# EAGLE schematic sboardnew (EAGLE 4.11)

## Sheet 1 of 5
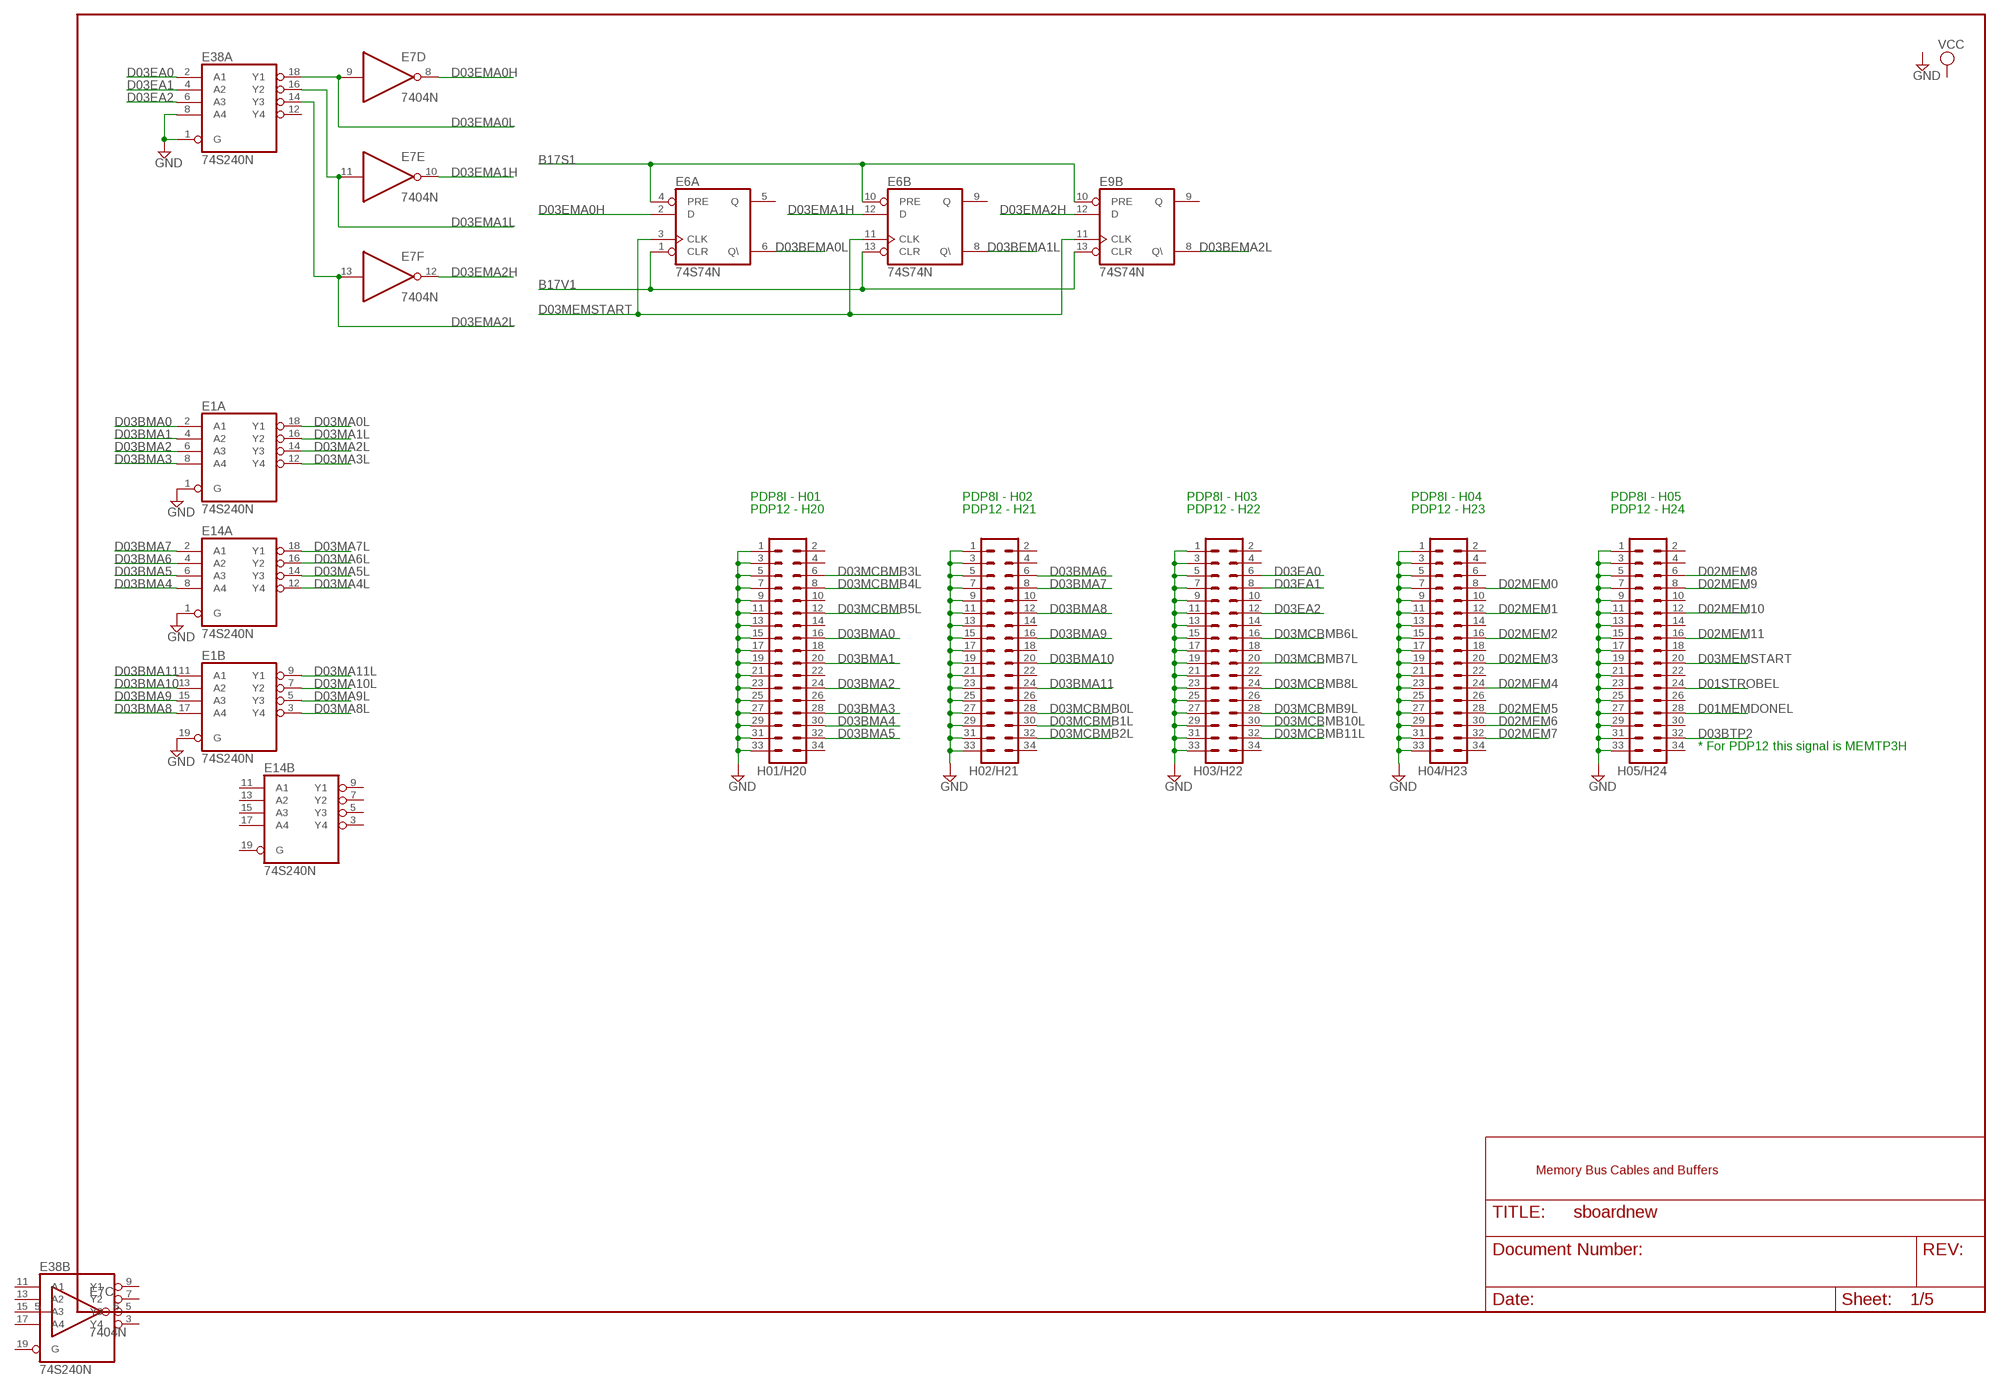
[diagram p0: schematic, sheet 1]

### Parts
E1  74S240N  [DIL20]
E6  74S74N  [DIL14]
E7  7404N  [DIL14]
E9  74S74N  [DIL14]
E14  74S240N  [DIL20]
E38  74S240N  [DIL20]
H01/H20  MA17-2  [MA17-2]
H02/H21  MA17-2  [MA17-2]
H03/H22  MA17-2  [MA17-2]
H04/H23  MA17-2  [MA17-2]
H05/H24  MA17-2  [MA17-2]

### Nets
B17S1: E6.4(A:PRE) E6.10(B:PRE) E9.10(B:PRE) ; also sheet 3,4
B17V1: E6.1(A:CLR) E6.13(B:CLR) E9.13(B:CLR) ; also sheet 3,4
D01MEMDONEL: H05/H24.28 ; also sheet 4
D01STROBEL: H05/H24.24 ; also sheet 4
D02MEM0: H04/H23.8 ; also sheet 3
D02MEM1: H04/H23.12 ; also sheet 3
D02MEM2: H04/H23.16 ; also sheet 3
D02MEM3: H04/H23.20 ; also sheet 3
D02MEM4: H04/H23.24 ; also sheet 3
D02MEM5: H04/H23.28 ; also sheet 3
D02MEM6: H04/H23.30 ; also sheet 3
D02MEM7: H04/H23.32 ; also sheet 3
D02MEM8: H05/H24.6 ; also sheet 3
D02MEM9: H05/H24.8 ; also sheet 3
D02MEM10: H05/H24.12 ; also sheet 3
D02MEM11: H05/H24.16 ; also sheet 3
D03BEMA0L: E6.6(A:Q\) ; also sheet 5
D03BEMA1L: E6.8(B:Q\) ; also sheet 5
D03BEMA2L: E9.8(B:Q\) ; also sheet 5
D03BMA0: E1.2(A:A1) H01/H20.16
D03BMA1: E1.4(A:A2) H01/H20.20
D03BMA2: E1.6(A:A3) H01/H20.24
D03BMA3: E1.8(A:A4) H01/H20.28
D03BMA4: E14.8(A:A4) H01/H20.30
D03BMA5: E14.6(A:A3) H01/H20.32
D03BMA6: E14.4(A:A2) H02/H21.6
D03BMA7: E14.2(A:A1) H02/H21.8
D03BMA8: E1.17(B:A4) H02/H21.12
D03BMA9: E1.15(B:A3) H02/H21.16
D03BMA10: E1.13(B:A2) H02/H21.20
D03BMA11: E1.11(B:A1) H02/H21.24
D03BTP2: H05/H24.32 ; also sheet 4
D03EA0: E38.2(A:A1) H03/H22.6
D03EA1: E38.4(A:A2) H03/H22.8
D03EA2: E38.6(A:A3) H03/H22.12
D03EMA0H: E6.2(A:D) E7.8(D:O) ; also sheet 4
D03EMA0L: E7.9(D:I) E38.18(A:Y1) ; also sheet 4
D03EMA1H: E6.12(B:D) E7.10(E:O) ; also sheet 4
D03EMA1L: E7.11(E:I) E38.16(A:Y2) ; also sheet 4
D03EMA2H: E7.12(F:O) E9.12(B:D) ; also sheet 4
D03EMA2L: E7.13(F:I) E38.14(A:Y3) ; also sheet 4
D03MA0L: E1.18(A:Y1) ; also sheet 5
D03MA1L: E1.16(A:Y2) ; also sheet 5
D03MA2L: E1.14(A:Y3) ; also sheet 5
D03MA3L: E1.12(A:Y4) ; also sheet 5
D03MA4L: E14.12(A:Y4) ; also sheet 5
D03MA5L: E14.14(A:Y3) ; also sheet 5
D03MA6L: E14.16(A:Y2) ; also sheet 5
D03MA7L: E14.18(A:Y1) ; also sheet 5
D03MA8L: E1.3(B:Y4) ; also sheet 5
D03MA9L: E1.5(B:Y3) ; also sheet 5
D03MA10L: E1.7(B:Y2) ; also sheet 5
D03MA11L: E1.9(B:Y1) ; also sheet 5
D03MCBMB0L: H02/H21.28 ; also sheet 2
D03MCBMB1L: H02/H21.30 ; also sheet 2
D03MCBMB2L: H02/H21.32 ; also sheet 2
D03MCBMB3L: H01/H20.6 ; also sheet 2
D03MCBMB4L: H01/H20.8 ; also sheet 2
D03MCBMB5L: H01/H20.12 ; also sheet 2
D03MCBMB6L: H03/H22.16 ; also sheet 2
D03MCBMB7L: H03/H22.20 ; also sheet 2
D03MCBMB8L: H03/H22.24 ; also sheet 2
D03MCBMB9L: H03/H22.28 ; also sheet 2
D03MCBMB10L: H03/H22.30 ; also sheet 2
D03MCBMB11L: H03/H22.32 ; also sheet 2
D03MEMSTART: E6.3(A:CLK) E6.11(B:CLK) E9.11(B:CLK) H05/H24.20 ; also sheet 4
GND [Power]: E1.1(A:G) E1.19(B:G) E14.1(A:G) E38.1(A:G) E38.8(A:A4) H01/H20.1 H01/H20.3 H01/H20.5 H01/H20.7 H01/H20.9 H01/H20.11 H01/H20.13 H01/H20.15 H01/H20.17 H01/H20.19 H01/H20.21 H01/H20.23 H01/H20.25 H01/H20.27 H01/H20.29 H01/H20.31 H01/H20.33 H02/H21.1 H02/H21.3 H02/H21.5 H02/H21.7 H02/H21.9 H02/H21.11 H02/H21.13 H02/H21.15 H02/H21.17 H02/H21.19 H02/H21.21 H02/H21.23 H02/H21.25 H02/H21.27 H02/H21.29 H02/H21.31 H02/H21.33 H03/H22.1 H03/H22.3 H03/H22.5 H03/H22.7 H03/H22.9 H03/H22.11 H03/H22.13 H03/H22.15 H03/H22.17 H03/H22.19 H03/H22.21 H03/H22.23 H03/H22.25 H03/H22.27 H03/H22.29 H03/H22.31 H03/H22.33 H04/H23.1 H04/H23.3 H04/H23.5 H04/H23.7 H04/H23.9 H04/H23.11 H04/H23.13 H04/H23.15 H04/H23.17 H04/H23.19 H04/H23.21 H04/H23.23 H04/H23.25 H04/H23.27 H04/H23.29 H04/H23.31 H04/H23.33 H05/H24.1 H05/H24.3 H05/H24.5 H05/H24.7 H05/H24.9 H05/H24.11 H05/H24.13 H05/H24.15 H05/H24.17 H05/H24.19 H05/H24.21 H05/H24.23 H05/H24.25 H05/H24.27 H05/H24.29 H05/H24.31 H05/H24.33 ; also sheet 3,4,5
Unconnected: E6.5(A:Q) E6.9(B:Q) H01/H20.2 H01/H20.4 H01/H20.10 H01/H20.14 H01/H20.18 H01/H20.22 H01/H20.26 H01/H20.34 H02/H21.2 H02/H21.4 H02/H21.10 H02/H21.14 H02/H21.18 H02/H21.22 H02/H21.26 H02/H21.34 H03/H22.2 H03/H22.4 H03/H22.10 H03/H22.14 H03/H22.18 H03/H22.22 H03/H22.26 H03/H22.34 H04/H23.2 H04/H23.4 H04/H23.6 H04/H23.10 H04/H23.14 H04/H23.18 H04/H23.22 H04/H23.26 H04/H23.34 H05/H24.2 H05/H24.4 H05/H24.10 H05/H24.14 H05/H24.18 H05/H24.22 H05/H24.26 H05/H24.30 H05/H24.34

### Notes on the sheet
- PDP8I - H01 | PDP8I - H02 | PDP8I - H03 | PDP8I - H04 | PDP8I - H05
- PDP12 - H20 | PDP12 - H21 | PDP12 - H22 | PDP12 - H23 | PDP12 - H24
- * For PDP12 this signal is MEMTP3H
- Memory Bus Cables and Buffers

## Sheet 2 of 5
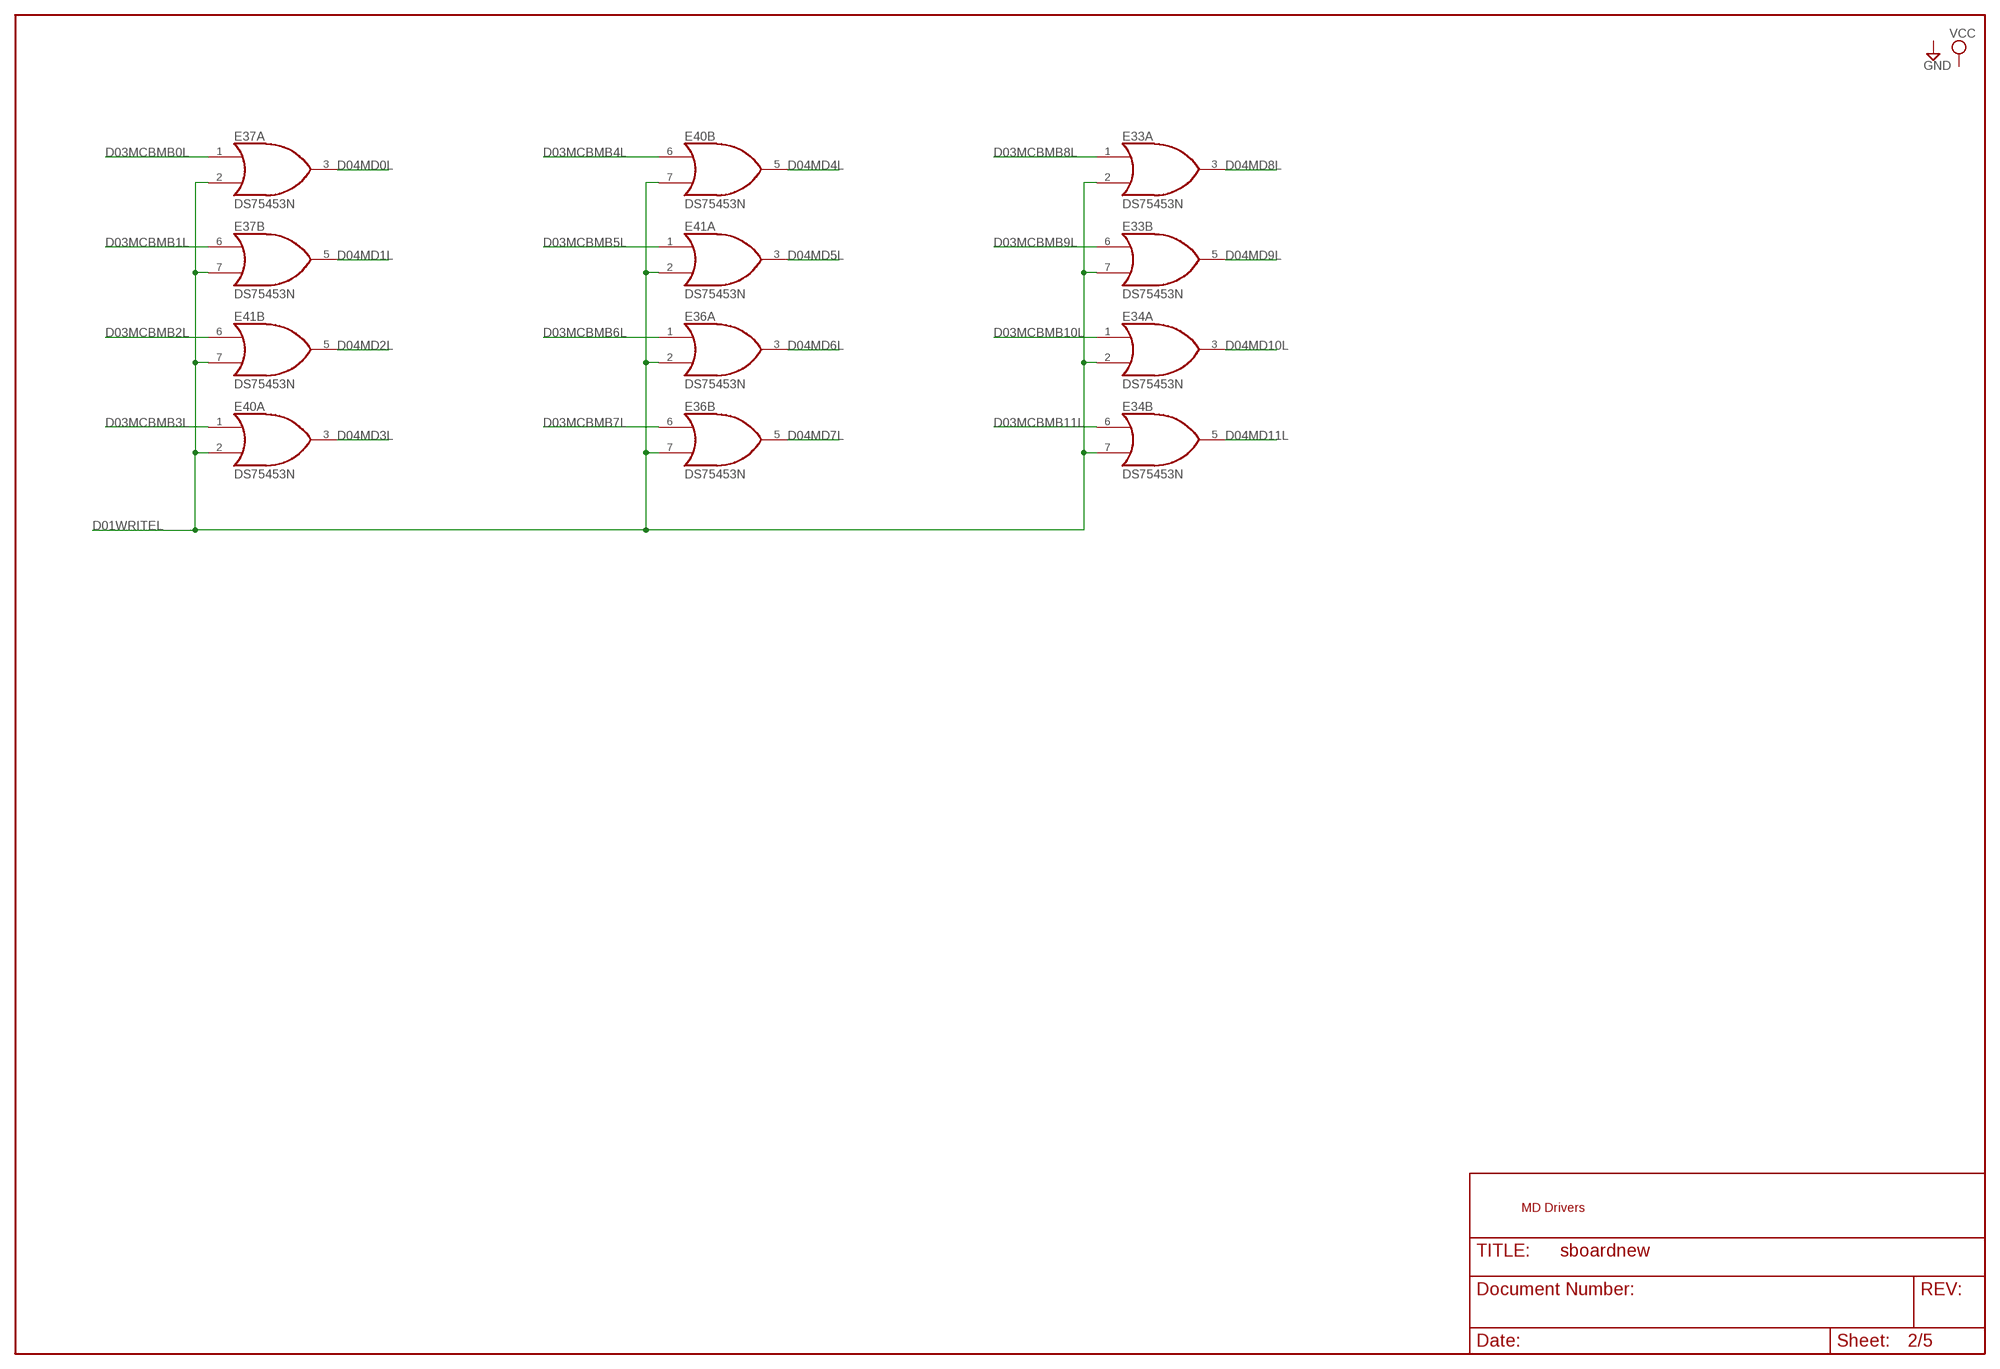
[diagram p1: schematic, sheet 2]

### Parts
E33  DS75453N  [DIL08]
E34  DS75453N  [DIL08]
E36  DS75453N  [DIL08]
E37  DS75453N  [DIL08]
E40  DS75453N  [DIL08]
E41  DS75453N  [DIL08]

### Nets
D01WRITEL: E33.2(A:I1) E33.7(B:I1) E34.2(A:I1) E34.7(B:I1) E36.2(A:I1) E36.7(B:I1) E37.2(A:I1) E37.7(B:I1) E40.2(A:I1) E40.7(B:I1) E41.2(A:I1) E41.7(B:I1) ; also sheet 3,5
D03MCBMB0L: E37.1(A:I0) ; also sheet 1
D03MCBMB1L: E37.6(B:I0) ; also sheet 1
D03MCBMB2L: E41.6(B:I0) ; also sheet 1
D03MCBMB3L: E40.1(A:I0) ; also sheet 1
D03MCBMB4L: E40.6(B:I0) ; also sheet 1
D03MCBMB5L: E41.1(A:I0) ; also sheet 1
D03MCBMB6L: E36.1(A:I0) ; also sheet 1
D03MCBMB7L: E36.6(B:I0) ; also sheet 1
D03MCBMB8L: E33.1(A:I0) ; also sheet 1
D03MCBMB9L: E33.6(B:I0) ; also sheet 1
D03MCBMB10L: E34.1(A:I0) ; also sheet 1
D03MCBMB11L: E34.6(B:I0) ; also sheet 1
D04MD0L: E37.3(A:O) ; also sheet 3,5
D04MD1L: E37.5(B:O) ; also sheet 3,5
D04MD2L: E41.5(B:O) ; also sheet 3,5
D04MD3L: E40.3(A:O) ; also sheet 3,5
D04MD4L: E40.5(B:O) ; also sheet 3,5
D04MD5L: E41.3(A:O) ; also sheet 3,5
D04MD6L: E36.3(A:O) ; also sheet 3,5
D04MD7L: E36.5(B:O) ; also sheet 3,5
D04MD8L: E33.3(A:O) ; also sheet 3,5
D04MD9L: E33.5(B:O) ; also sheet 3,5
D04MD10L: E34.3(A:O) ; also sheet 3,5
D04MD11L: E34.5(B:O) ; also sheet 3,5

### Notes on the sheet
- MD Drivers

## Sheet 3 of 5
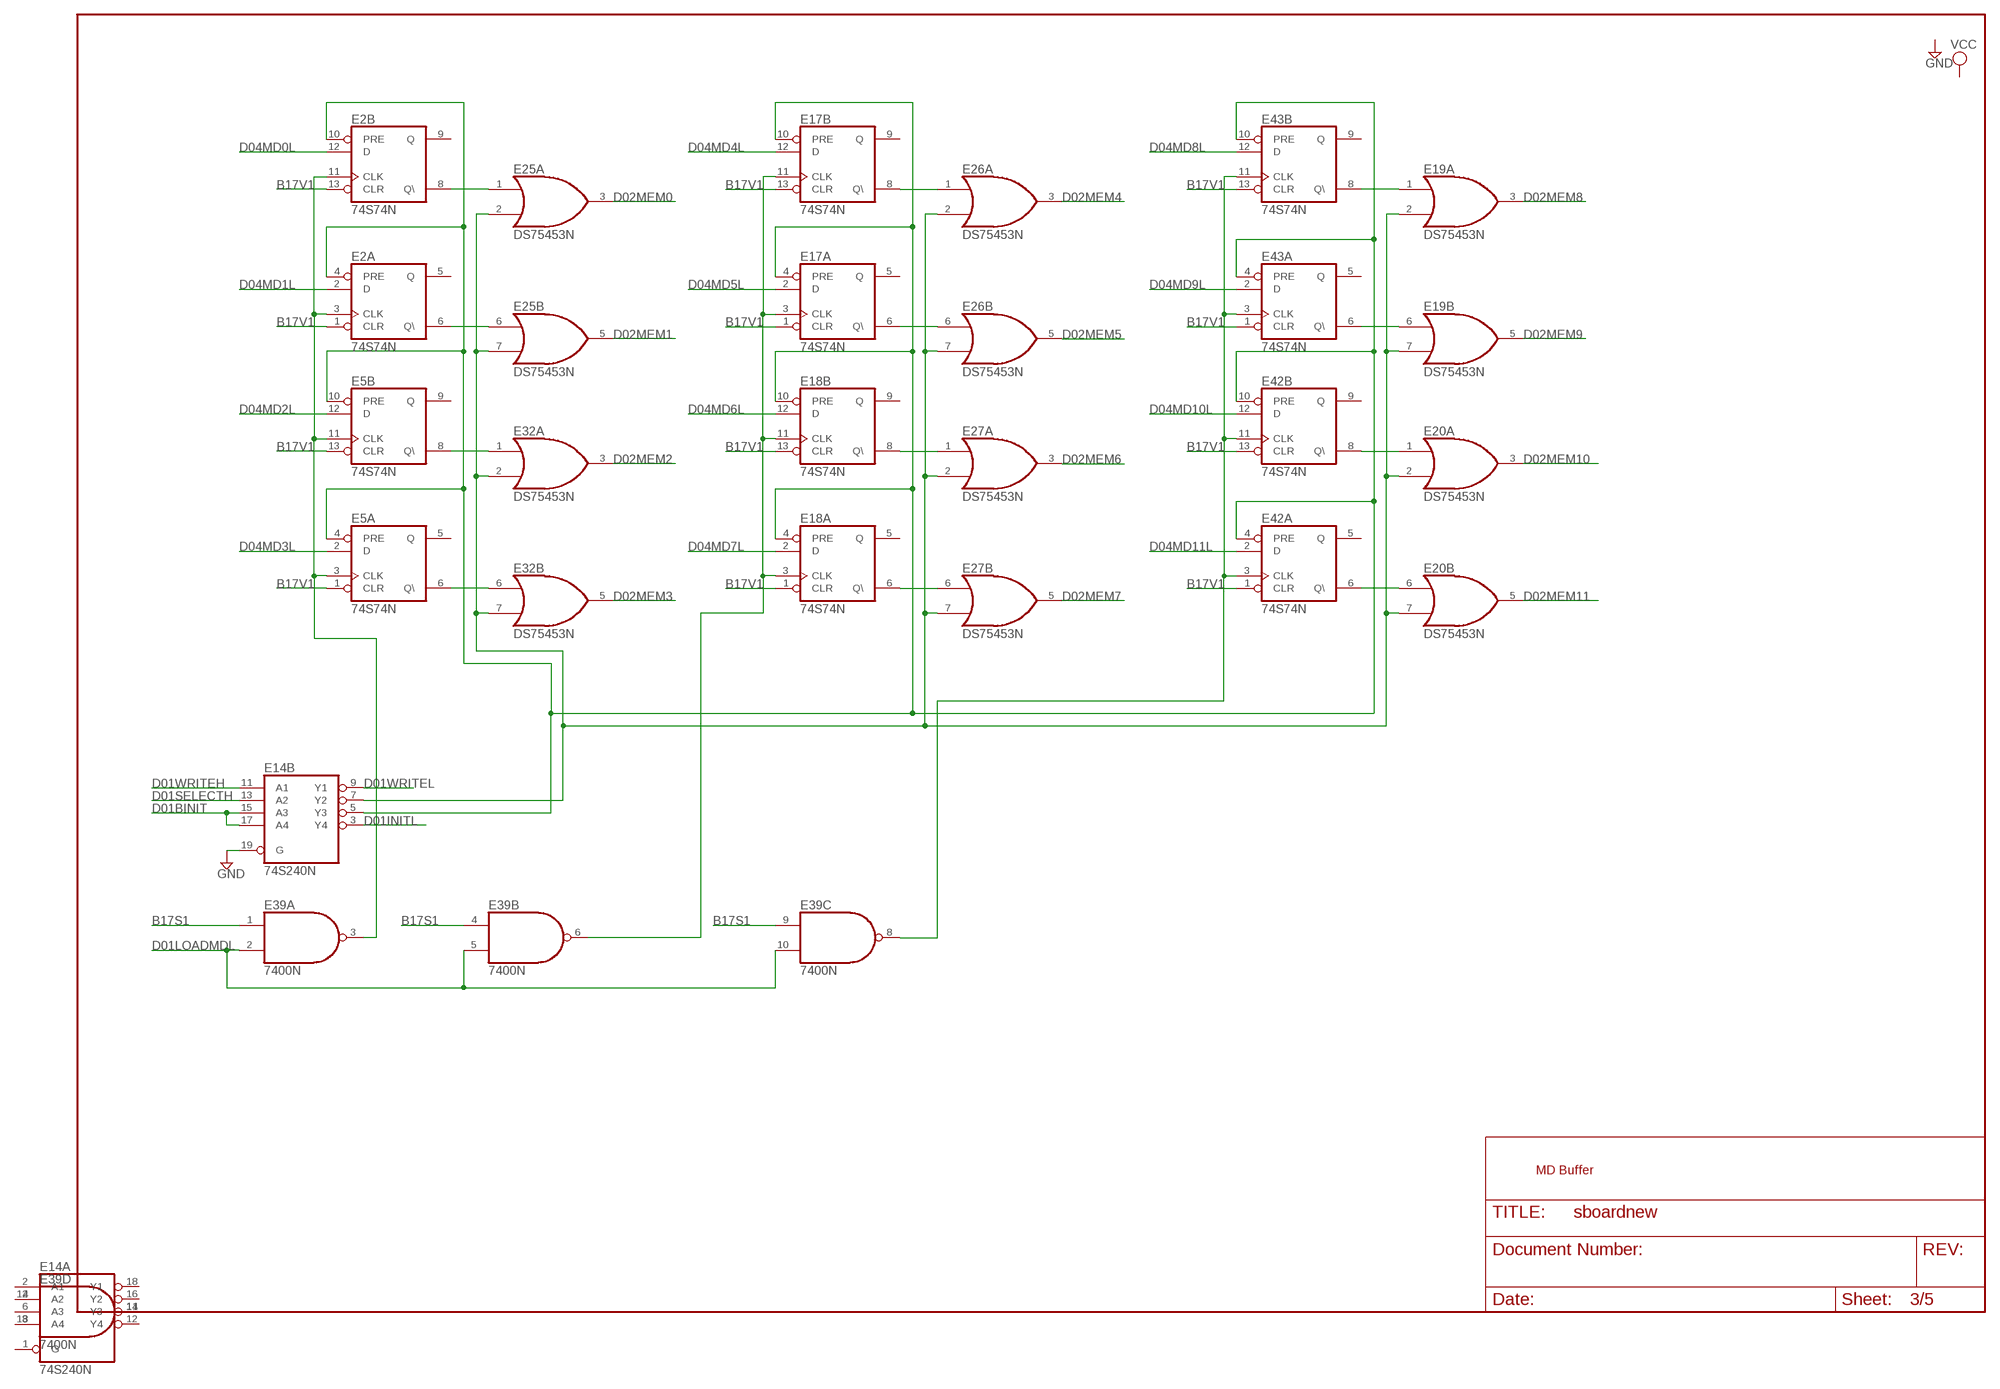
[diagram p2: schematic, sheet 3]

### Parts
E2  74S74N  [DIL14]
E5  74S74N  [DIL14]
E17  74S74N  [DIL14]
E18  74S74N  [DIL14]
E19  DS75453N  [DIL08]
E20  DS75453N  [DIL08]
E25  DS75453N  [DIL08]
E26  DS75453N  [DIL08]
E27  DS75453N  [DIL08]
E32  DS75453N  [DIL08]
E39  7400N  [DIL14]
E42  74S74N  [DIL14]
E43  74S74N  [DIL14]

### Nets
B17S1: E39.1(A:I0) E39.4(B:I0) E39.9(C:I0) ; also sheet 1,4
B17V1: E2.1(A:CLR) E2.13(B:CLR) E5.1(A:CLR) E5.13(B:CLR) E17.1(A:CLR) E17.13(B:CLR) E18.1(A:CLR) E18.13(B:CLR) E42.1(A:CLR) E42.13(B:CLR) E43.1(A:CLR) E43.13(B:CLR) ; also sheet 1,4
D01BINIT: E14.15(B:A3) E14.17(B:A4) ; also sheet 4
D01INITL: E14.3(B:Y4) ; also sheet 4
D01LOADMDL: E39.2(A:I1) E39.5(B:I1) E39.10(C:I1) ; also sheet 4
D01SELECTH: E14.13(B:A2) ; also sheet 4
D01WRITEH: E14.11(B:A1) ; also sheet 4
D01WRITEL: E14.9(B:Y1) ; also sheet 2,5
D02MEM0: E25.3(A:O) ; also sheet 1
D02MEM1: E25.5(B:O) ; also sheet 1
D02MEM2: E32.3(A:O) ; also sheet 1
D02MEM3: E32.5(B:O) ; also sheet 1
D02MEM4: E26.3(A:O) ; also sheet 1
D02MEM5: E26.5(B:O) ; also sheet 1
D02MEM6: E27.3(A:O) ; also sheet 1
D02MEM7: E27.5(B:O) ; also sheet 1
D02MEM8: E19.3(A:O) ; also sheet 1
D02MEM9: E19.5(B:O) ; also sheet 1
D02MEM10: E20.3(A:O) ; also sheet 1
D02MEM11: E20.5(B:O) ; also sheet 1
D04MD0L: E2.12(B:D) ; also sheet 2,5
D04MD1L: E2.2(A:D) ; also sheet 2,5
D04MD2L: E5.12(B:D) ; also sheet 2,5
D04MD3L: E5.2(A:D) ; also sheet 2,5
D04MD4L: E17.12(B:D) ; also sheet 2,5
D04MD5L: E17.2(A:D) ; also sheet 2,5
D04MD6L: E18.12(B:D) ; also sheet 2,5
D04MD7L: E18.2(A:D) ; also sheet 2,5
D04MD8L: E43.12(B:D) ; also sheet 2,5
D04MD9L: E43.2(A:D) ; also sheet 2,5
D04MD10L: E42.12(B:D) ; also sheet 2,5
D04MD11L: E42.2(A:D) ; also sheet 2,5
GND [Power]: E14.19(B:G) ; also sheet 1,4,5
N$8: E2.3(A:CLK) E2.11(B:CLK) E5.3(A:CLK) E5.11(B:CLK) E39.3(A:O)
N$12: E5.6(A:Q\) E32.6(B:I0)
N$14: E2.8(B:Q\) E25.1(A:I0)
N$15: E2.6(A:Q\) E25.6(B:I0)
N$16: E17.3(A:CLK) E17.11(B:CLK) E18.3(A:CLK) E18.11(B:CLK) E39.6(B:O)
N$17: E5.8(B:Q\) E32.1(A:I0)
N$21: E2.4(A:PRE) E2.10(B:PRE) E5.4(A:PRE) E5.10(B:PRE) E14.5(B:Y3) E17.4(A:PRE) E17.10(B:PRE) E18.4(A:PRE) E18.10(B:PRE) E42.4(A:PRE) E42.10(B:PRE) E43.4(A:PRE) E43.10(B:PRE)
N$22: E14.7(B:Y2) E19.2(A:I1) E19.7(B:I1) E20.2(A:I1) E20.7(B:I1) E25.2(A:I1) E25.7(B:I1) E26.2(A:I1) E26.7(B:I1) E27.2(A:I1) E27.7(B:I1) E32.2(A:I1) E32.7(B:I1)
N$24: E17.6(A:Q\) E26.6(B:I0)
N$25: E18.6(A:Q\) E27.6(B:I0)
N$26: E18.8(B:Q\) E27.1(A:I0)
N$27: E17.8(B:Q\) E26.1(A:I0)
N$29: E20.6(B:I0) E42.6(A:Q\)
N$30: E20.1(A:I0) E42.8(B:Q\)
N$41: E39.8(C:O) E42.3(A:CLK) E42.11(B:CLK) E43.3(A:CLK) E43.11(B:CLK)
N$67: E19.6(B:I0) E43.6(A:Q\)
N$68: E19.1(A:I0) E43.8(B:Q\)
Unconnected: E2.5(A:Q) E2.9(B:Q) E5.5(A:Q) E5.9(B:Q) E17.5(A:Q) E17.9(B:Q) E18.5(A:Q) E18.9(B:Q) E42.5(A:Q) E42.9(B:Q) E43.5(A:Q) E43.9(B:Q)

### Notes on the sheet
- MD Buffer

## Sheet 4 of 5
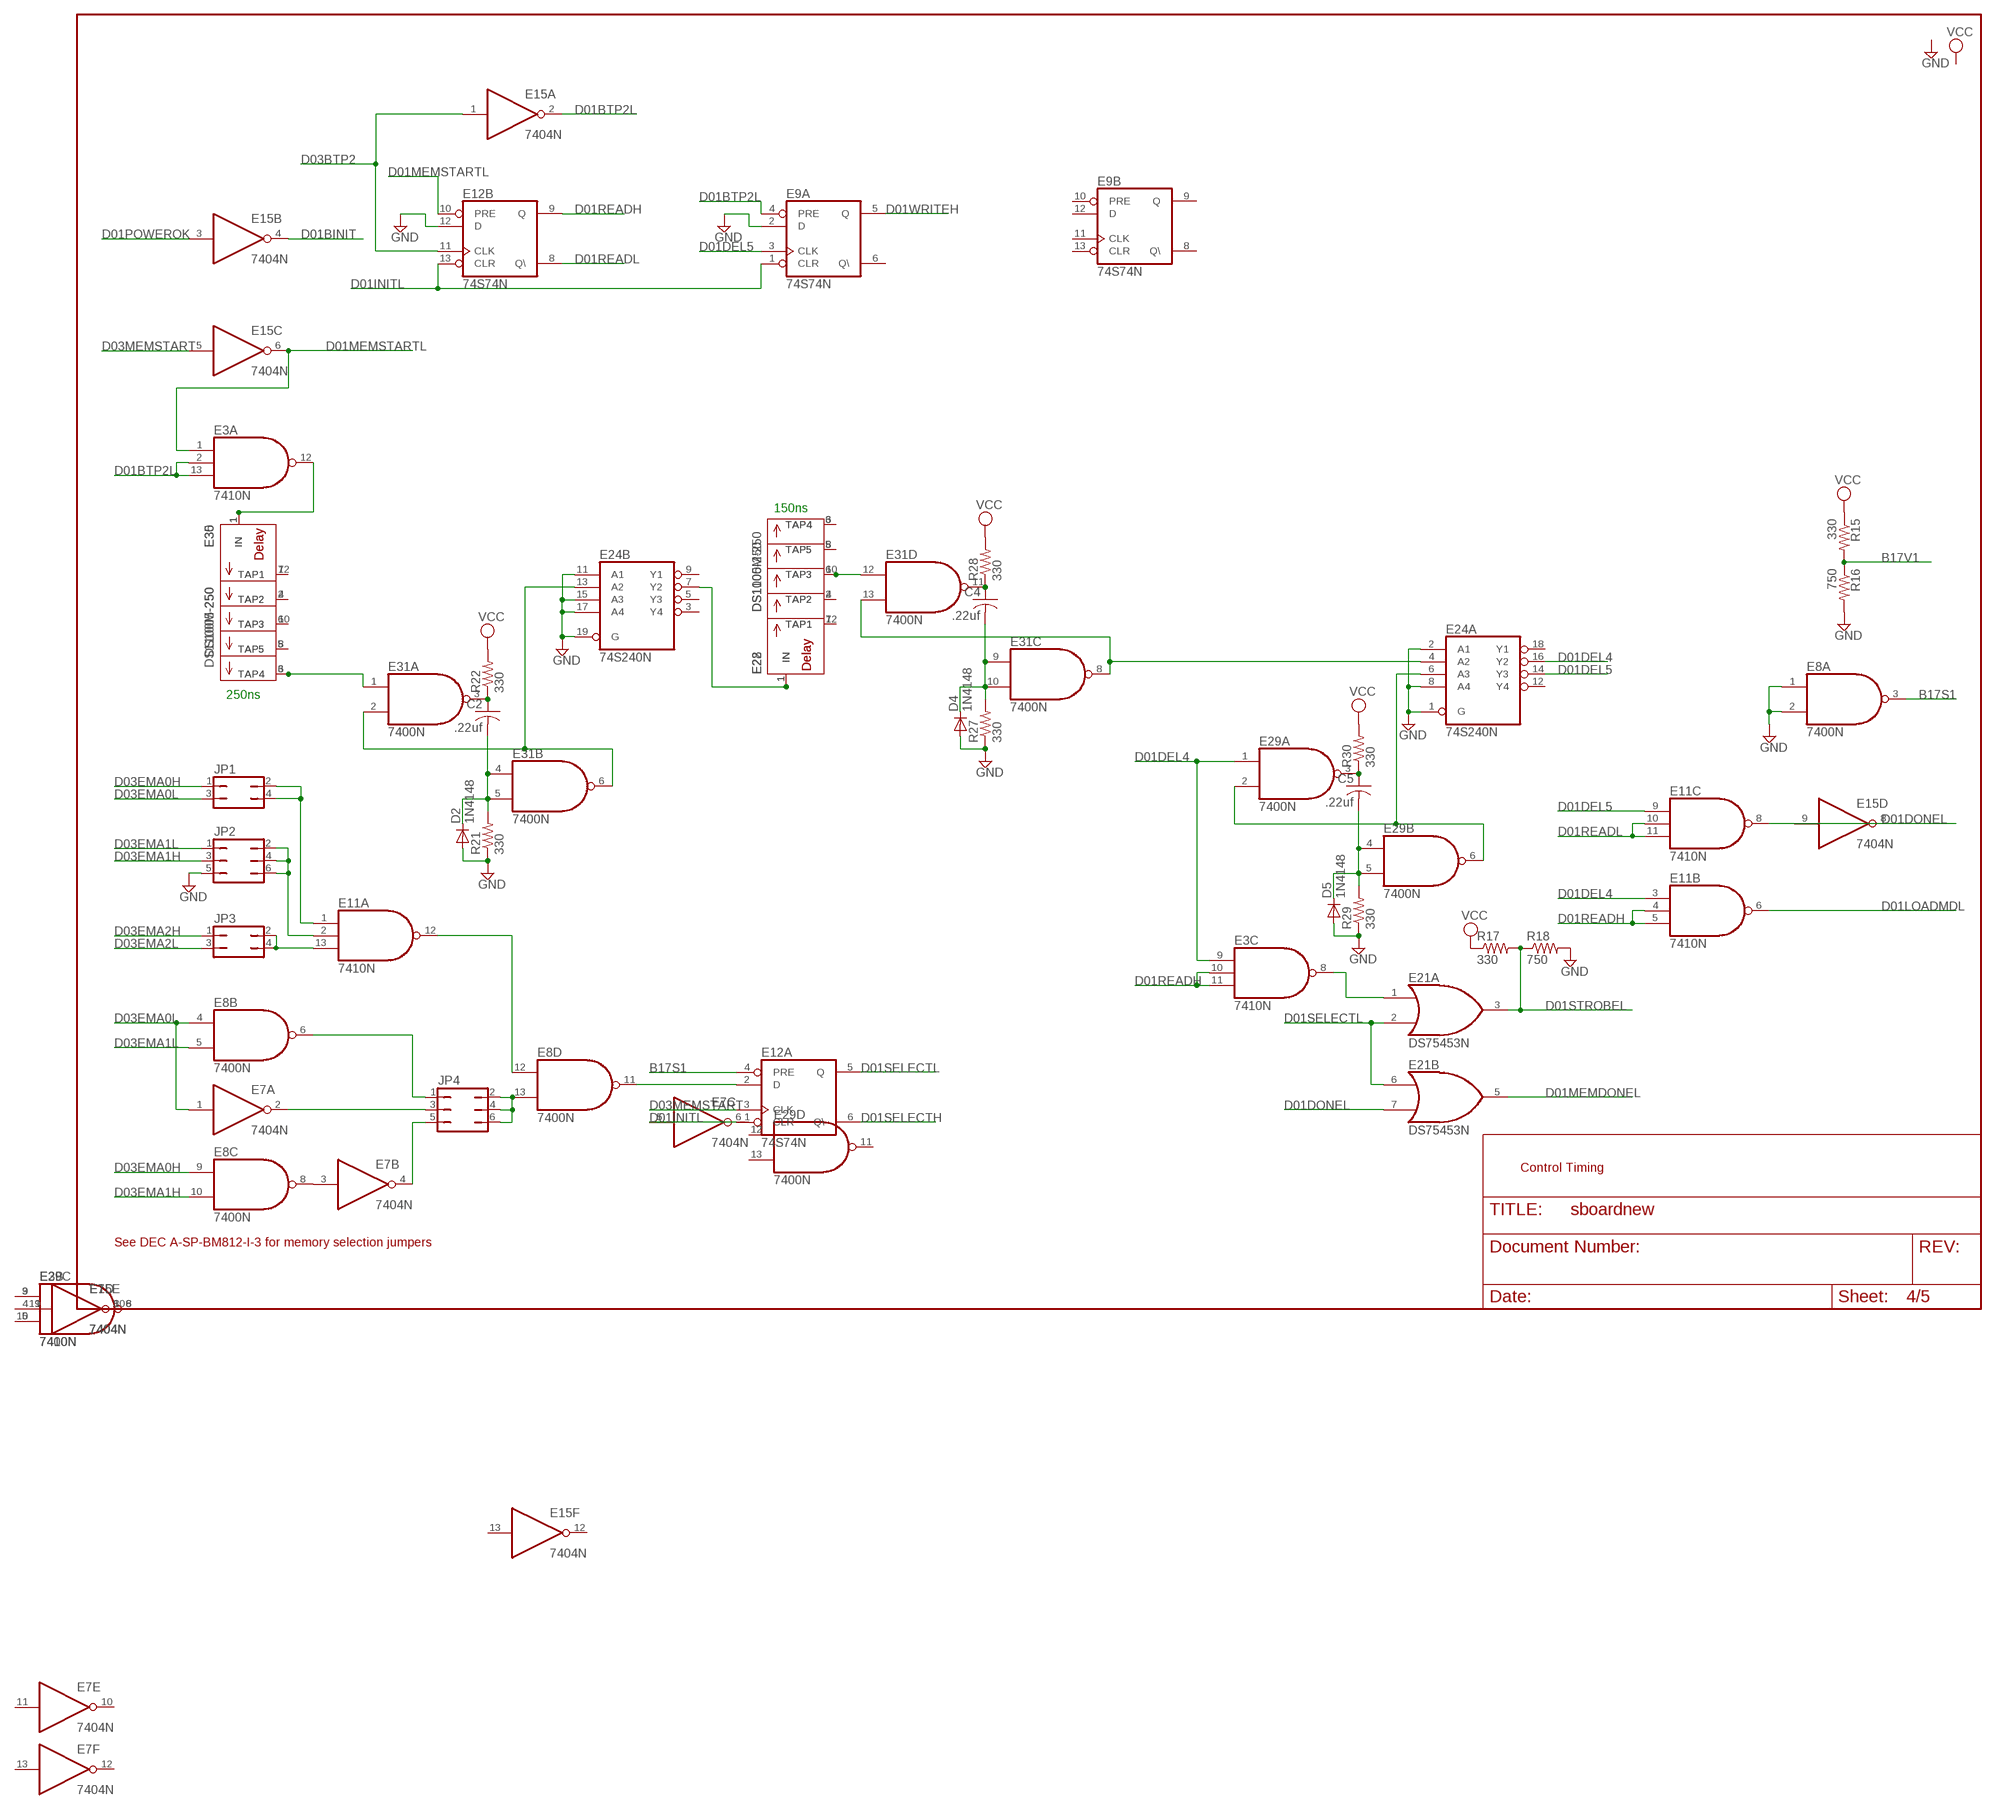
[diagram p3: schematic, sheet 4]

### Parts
C2  .22uf  C-US050-025X075  [C050-025X075]
C4  .22uf  C-US050-025X075  [C050-025X075]
C5  .22uf  C-US050-025X075  [C050-025X075]
D2  1N4148  [DO35-10]
D4  1N4148  [DO35-10]
D5  1N4148  [DO35-10]
E3  7410N  [DIL14]
E8  7400N  [DIL14]
E11  7410N  [DIL14]
E12  74S74N  [DIL14]
E15  7404N  [DIL14]
E21  DS75453N  [DIL08]
E22  DS1100M-250  MXD1000  [DIL08]
E24  74S240N  [DIL20]
E28  DS1005-250  MXD1000P  [DIL14]
E29  7400N  [DIL14]
E30  DS1005-250  MXD1000P  [DIL14]
E31  7400N  [DIL14]
E35  DS1100M-250  MXD1000  [DIL08]
JP1  JP2Q  [JP2Q]
JP2  JP3Q  [JP3Q]
JP3  JP2Q  [JP2Q]
JP4  JP3Q  [JP3Q]
R15  330  R-US_0207/10  [0207/10]
R16  750  R-US_0207/10  [0207/10]
R17  330  R-US_0207/10  [0207/10]
R18  750  R-US_0207/10  [0207/10]
R21  330  R-US_0207/10  [0207/10]
R22  330  R-US_0207/10  [0207/10]
R27  330  R-US_0207/10  [0207/10]
R28  330  R-US_0207/10  [0207/10]
R29  330  R-US_0207/10  [0207/10]
R30  330  R-US_0207/10  [0207/10]

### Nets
B17S1: E8.3(A:O) E12.4(A:PRE) ; also sheet 1,3
B17V1: R15.2 R16.1 ; also sheet 1,3
D01BINIT: E15.4(B:O) ; also sheet 3
D01BTP2L: E3.2(A:I1) E3.13(A:I2) E9.4(A:PRE) E15.2(A:O)
D01DEL2X: E22.1(IN) E24.7(B:Y2) E28.1(IN)
D01DEL4: E3.9(C:I0) E11.3(B:I0) E24.16(A:Y2) E29.1(A:I0)
D01DEL5: E9.3(A:CLK) E11.9(C:I0) E24.14(A:Y3)
D01DONEL: E11.8(C:O) E21.7(B:I1)
D01INITL: E9.1(A:CLR) E12.1(A:CLR) E12.13(B:CLR) ; also sheet 3
D01LOADMDL: E11.6(B:O) ; also sheet 3
D01MEMDONEL: E21.5(B:O) ; also sheet 1
D01MEMSTARTL: E3.1(A:I0) E12.10(B:PRE) E15.6(C:O)
D01POWEROK: E15.3(B:I) ; also sheet 5
D01READH: E3.10(C:I1) E3.11(C:I2) E11.4(B:I1) E11.5(B:I2) E12.9(B:Q)
D01READL: E11.10(C:I1) E11.11(C:I2) E12.8(B:Q\) ; also sheet 5
D01SELECTH: E12.6(A:Q\) ; also sheet 3
D01SELECTL: E12.5(A:Q) E21.2(A:I1) E21.6(B:I0)
D01SELL: E8.11(D:O) E12.2(A:D)
D01STROBEL: E21.3(A:O) R17.2 R18.1 ; also sheet 1
D01WRITEH: E9.5(A:Q) ; also sheet 3
D03BTP2: E12.11(B:CLK) E15.1(A:I) ; also sheet 1
D03EMA0H: E8.9(C:I0) JP1.1 ; also sheet 1
D03EMA0L: E7.1(A:I) E8.4(B:I0) JP1.3 ; also sheet 1
D03EMA1H: E8.10(C:I1) JP2.3 ; also sheet 1
D03EMA1L: E8.5(B:I1) JP2.1 ; also sheet 1
D03EMA2H: JP3.1 ; also sheet 1
D03EMA2L: JP3.3 ; also sheet 1
D03MEMSTART: E12.3(A:CLK) E15.5(C:I) ; also sheet 1
GND [Power]: D2.A D4.A D5.A E8.1(A:I0) E8.2(A:I1) E9.2(A:D) E12.12(B:D) E24.1(A:G) E24.2(A:A1) E24.8(A:A4) E24.11(B:A1) E24.15(B:A3) E24.17(B:A4) E24.19(B:G) JP2.5 R16.2 R18.2 R21.1 R27.1 R29.1 ; also sheet 1,3,5
N$2: E22.2(TAP2) E28.4(TAP2)
N$5: C5.2 D5.C E29.4(B:I0) E29.5(B:I1) R29.2
N$7: E8.13(D:I1) JP4.2 JP4.4 JP4.6
N$9: C2.2 D2.C E31.4(B:I0) E31.5(B:I1) R21.2
N$10: E30.12(TAP1) E35.7(TAP1)
N$20: C2.1 E31.3(A:O) R22.1
N$23: E24.13(B:A2) E31.2(A:I1) E31.6(B:O)
N$31: E30.6(TAP4) E31.1(A:I0) E35.3(TAP4)
N$33: C4.2 D4.C E31.9(C:I0) E31.10(C:I1) R27.2
N$34: C4.1 E31.11(D:O) R28.1
N$35: E3.12(A:O) E30.1(IN) E35.1(IN)
N$37: E24.4(A:A2) E31.8(C:O) E31.13(D:I1)
N$38: E22.6(TAP3) E28.10(TAP3) E31.12(D:I0)
N$39: C5.1 E29.3(A:O) R30.1
N$40: E24.6(A:A3) E29.2(A:I1) E29.6(B:O)
N$48: E22.7(TAP1) E28.12(TAP1)
N$49: E22.3(TAP4) E28.6(TAP4)
N$50: E22.5(TAP5) E28.8(TAP5)
N$51: E30.4(TAP2) E35.2(TAP2)
N$52: E30.10(TAP3) E35.6(TAP3)
N$53: E30.8(TAP5) E35.5(TAP5)
N$73: E8.6(B:O) JP4.1
N$94: E3.8(C:O) E21.1(A:I0)
N$103: E7.2(A:O) JP4.3
N$108: E7.3(B:I) E8.8(C:O)
N$111: E7.4(B:O) JP4.5
N$113: E11.13(A:I2) JP3.2 JP3.4
N$128: E11.2(A:I1) JP2.2 JP2.4 JP2.6
N$129: E11.1(A:I0) JP1.2 JP1.4
N$132: E8.12(D:I0) E11.12(A:O)
VCC [Power]: R15.1 R17.1 R22.2 R28.2 R30.2 ; also sheet 5
Unconnected: E9.6(A:Q\) E9.9(B:Q) E24.3(B:Y4) E24.5(B:Y3) E24.9(B:Y1) E24.12(A:Y4) E24.18(A:Y1) E28.2(NC) E28.3(NC) E28.5(NC) E28.9(NC) E28.11(NC) E28.13(NC) E30.2(NC) E30.3(NC) E30.5(NC) E30.9(NC) E30.11(NC) E30.13(NC)

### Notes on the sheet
- 150ns
- 250ns
- Control Timing
- See DEC A-SP-BM812-I-3 for memory selection jumpers

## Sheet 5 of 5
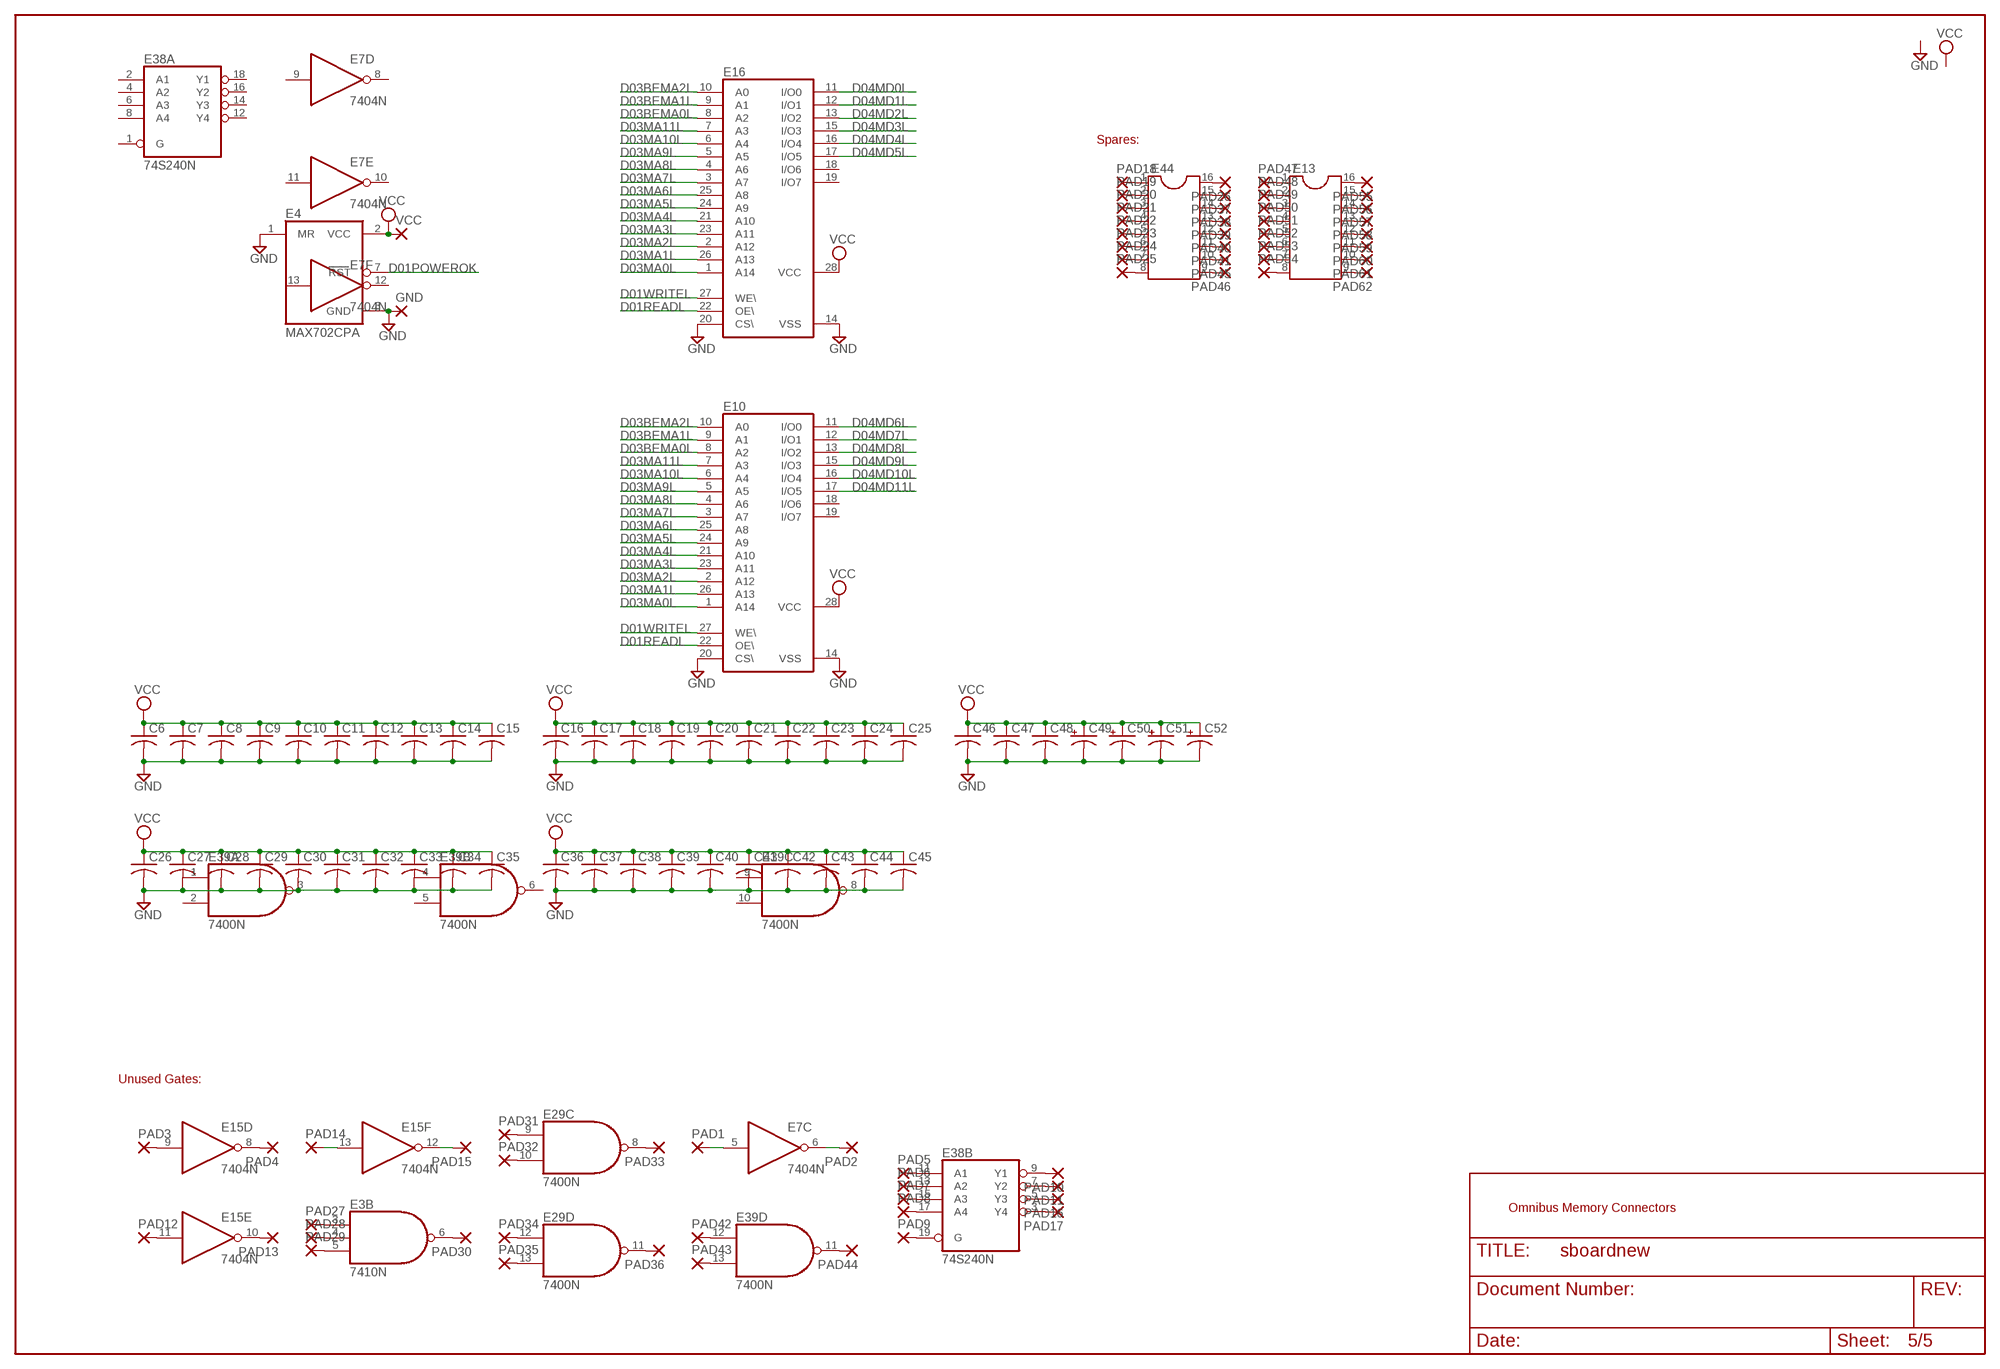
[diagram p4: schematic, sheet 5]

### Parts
C6  C-US050-025X075  [C050-025X075]
C7  C-US050-025X075  [C050-025X075]
C8  C-US050-025X075  [C050-025X075]
C9  C-US050-025X075  [C050-025X075]
C10  C-US050-025X075  [C050-025X075]
C11  C-US050-025X075  [C050-025X075]
C12  C-US050-025X075  [C050-025X075]
C13  C-US050-025X075  [C050-025X075]
C14  C-US050-025X075  [C050-025X075]
C15  C-US050-025X075  [C050-025X075]
C16  C-US050-025X075  [C050-025X075]
C17  C-US050-025X075  [C050-025X075]
C18  C-US050-025X075  [C050-025X075]
C19  C-US050-025X075  [C050-025X075]
C20  C-US050-025X075  [C050-025X075]
C21  C-US050-025X075  [C050-025X075]
C22  C-US050-025X075  [C050-025X075]
C23  C-US050-025X075  [C050-025X075]
C24  C-US050-025X075  [C050-025X075]
C25  C-US050-025X075  [C050-025X075]
C26  C-US050-025X075  [C050-025X075]
C27  C-US050-025X075  [C050-025X075]
C28  C-US050-025X075  [C050-025X075]
C29  C-US050-025X075  [C050-025X075]
C30  C-US050-025X075  [C050-025X075]
C31  C-US050-025X075  [C050-025X075]
C32  C-US050-025X075  [C050-025X075]
C33  C-US050-025X075  [C050-025X075]
C34  C-US050-025X075  [C050-025X075]
C35  C-US050-025X075  [C050-025X075]
C36  C-US050-025X075  [C050-025X075]
C37  C-US050-025X075  [C050-025X075]
C38  C-US050-025X075  [C050-025X075]
C39  C-US050-025X075  [C050-025X075]
C40  C-US050-025X075  [C050-025X075]
C41  C-US050-025X075  [C050-025X075]
C42  C-US050-025X075  [C050-025X075]
C43  C-US050-025X075  [C050-025X075]
C44  C-US050-025X075  [C050-025X075]
C45  C-US050-025X075  [C050-025X075]
C46  C-US050-025X075  [C050-025X075]
C47  C-US050-025X075  [C050-025X075]
C48  C-US050-025X075  [C050-025X075]
C49  CPOL-USE22-6AXIAL  [E22-6]
C50  CPOL-USE22-6AXIAL  [E22-6]
C51  CPOL-USE22-6AXIAL  [E22-6]
C52  CPOL-USE22-6AXIAL  [E22-6]
E4  MAX702CPA  [DIL08]
E10  62256P  [DIL28-6]
E13  DIL16  [DIL16]
E16  62256P  [DIL28-6]
E44  DIL16  [DIL16]
GND  2,15/1,0  [2,15/1,0]
PAD1  1,6/0,8  [1,6/0,8]
PAD2  1,6/0,8  [1,6/0,8]
PAD3  1,6/0,8  [1,6/0,8]
PAD4  1,6/0,8  [1,6/0,8]
PAD5  1,6/0,8  [1,6/0,8]
PAD6  1,6/0,8  [1,6/0,8]
PAD7  1,6/0,8  [1,6/0,8]
PAD8  1,6/0,8  [1,6/0,8]
PAD9  1,6/0,8  [1,6/0,8]
PAD10  1,6/0,8  [1,6/0,8]
PAD11  1,6/0,8  [1,6/0,8]
PAD12  1,6/0,8  [1,6/0,8]
PAD13  1,6/0,8  [1,6/0,8]
PAD14  1,6/0,8  [1,6/0,8]
PAD15  1,6/0,8  [1,6/0,8]
PAD16  1,6/0,8  [1,6/0,8]
PAD17  1,6/0,8  [1,6/0,8]
PAD18  1,6/0,8  [1,6/0,8]
PAD19  1,6/0,8  [1,6/0,8]
PAD20  1,6/0,8  [1,6/0,8]
PAD21  1,6/0,8  [1,6/0,8]
PAD22  1,6/0,8  [1,6/0,8]
PAD23  1,6/0,8  [1,6/0,8]
PAD24  1,6/0,8  [1,6/0,8]
PAD25  1,6/0,8  [1,6/0,8]
PAD26  1,6/0,8  [1,6/0,8]
PAD27  1,6/0,8  [1,6/0,8]
PAD28  1,6/0,8  [1,6/0,8]
PAD29  1,6/0,8  [1,6/0,8]
PAD30  1,6/0,8  [1,6/0,8]
PAD31  1,6/0,8  [1,6/0,8]
PAD32  1,6/0,8  [1,6/0,8]
PAD33  1,6/0,8  [1,6/0,8]
PAD34  1,6/0,8  [1,6/0,8]
PAD35  1,6/0,8  [1,6/0,8]
PAD36  1,6/0,8  [1,6/0,8]
PAD37  1,6/0,8  [1,6/0,8]
PAD38  1,6/0,8  [1,6/0,8]
PAD39  1,6/0,8  [1,6/0,8]
PAD40  1,6/0,8  [1,6/0,8]
PAD41  1,6/0,8  [1,6/0,8]
PAD42  1,6/0,8  [1,6/0,8]
PAD43  1,6/0,8  [1,6/0,8]
PAD44  1,6/0,8  [1,6/0,8]
PAD45  1,6/0,8  [1,6/0,8]
PAD46  1,6/0,8  [1,6/0,8]
PAD47  1,6/0,8  [1,6/0,8]
PAD48  1,6/0,8  [1,6/0,8]
PAD49  1,6/0,8  [1,6/0,8]
PAD50  1,6/0,8  [1,6/0,8]
PAD51  1,6/0,8  [1,6/0,8]
PAD52  1,6/0,8  [1,6/0,8]
PAD53  1,6/0,8  [1,6/0,8]
PAD54  1,6/0,8  [1,6/0,8]
PAD55  1,6/0,8  [1,6/0,8]
PAD56  1,6/0,8  [1,6/0,8]
PAD57  1,6/0,8  [1,6/0,8]
PAD58  1,6/0,8  [1,6/0,8]
PAD59  1,6/0,8  [1,6/0,8]
PAD60  1,6/0,8  [1,6/0,8]
PAD61  1,6/0,8  [1,6/0,8]
PAD62  1,6/0,8  [1,6/0,8]
VCC  2,15/1,0  [2,15/1,0]

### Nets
D01POWEROK: E4.7(RST) ; also sheet 4
D01READL: E10.22(OE\) E16.22(OE\) ; also sheet 4
D01WRITEL: E10.27(WE\) E16.27(WE\) ; also sheet 2,3
D03BEMA0L: E10.8(A2) E16.8(A2) ; also sheet 1
D03BEMA1L: E10.9(A1) E16.9(A1) ; also sheet 1
D03BEMA2L: E10.10(A0) E16.10(A0) ; also sheet 1
D03MA0L: E10.1(A14) E16.1(A14) ; also sheet 1
D03MA1L: E10.26(A13) E16.26(A13) ; also sheet 1
D03MA2L: E10.2(A12) E16.2(A12) ; also sheet 1
D03MA3L: E10.23(A11) E16.23(A11) ; also sheet 1
D03MA4L: E10.21(A10) E16.21(A10) ; also sheet 1
D03MA5L: E10.24(A9) E16.24(A9) ; also sheet 1
D03MA6L: E10.25(A8) E16.25(A8) ; also sheet 1
D03MA7L: E10.3(A7) E16.3(A7) ; also sheet 1
D03MA8L: E10.4(A6) E16.4(A6) ; also sheet 1
D03MA9L: E10.5(A5) E16.5(A5) ; also sheet 1
D03MA10L: E10.6(A4) E16.6(A4) ; also sheet 1
D03MA11L: E10.7(A3) E16.7(A3) ; also sheet 1
D04MD0L: E16.11(I/O0) ; also sheet 2,3
D04MD1L: E16.12(I/O1) ; also sheet 2,3
D04MD2L: E16.13(I/O2) ; also sheet 2,3
D04MD3L: E16.15(I/O3) ; also sheet 2,3
D04MD4L: E16.16(I/O4) ; also sheet 2,3
D04MD5L: E16.17(I/O5) ; also sheet 2,3
D04MD6L: E10.11(I/O0) ; also sheet 2,3
D04MD7L: E10.12(I/O1) ; also sheet 2,3
D04MD8L: E10.13(I/O2) ; also sheet 2,3
D04MD9L: E10.15(I/O3) ; also sheet 2,3
D04MD10L: E10.16(I/O4) ; also sheet 2,3
D04MD11L: E10.17(I/O5) ; also sheet 2,3
GND [Power]: C6.2 C7.2 C8.2 C9.2 C10.2 C11.2 C12.2 C13.2 C14.2 C15.2 C16.2 C17.2 C18.2 C19.2 C20.2 C21.2 C22.2 C23.2 C24.2 C25.2 C26.2 C27.2 C28.2 C29.2 C30.2 C31.2 C32.2 C33.2 C34.2 C35.2 C36.2 C37.2 C38.2 C39.2 C40.2 C41.2 C42.2 C43.2 C44.2 C45.2 C46.2 C47.2 C48.2 C49.- C50.- C51.- C52.- E4.1(MR) E4.3(GND) E10.14(VSS) E10.20(CS\) E16.14(VSS) E16.20(CS\) GND.1(P) ; also sheet 1,3,4
N$1: E7.5(C:I) PAD1.1(P)
N$3: E7.6(C:O) PAD2.1(P)
N$4: E15.9(D:I) PAD3.1(P)
N$6: E15.8(D:O) PAD4.1(P)
N$11: E38.11(B:A1) PAD5.1(P)
N$13: E38.13(B:A2) PAD6.1(P)
N$18: E38.15(B:A3) PAD7.1(P)
N$19: E38.19(B:G) PAD9.1(P)
N$28: E38.9(B:Y1) PAD10.1(P)
N$32: E38.7(B:Y2) PAD11.1(P)
N$36: E38.5(B:Y3) PAD16.1(P)
N$42: E38.3(B:Y4) PAD17.1(P)
N$43: E38.17(B:A4) PAD8.1(P)
N$44: E44.1 PAD18.1(P)
N$45: E44.2 PAD19.1(P)
N$46: E44.3 PAD20.1(P)
N$47: E44.4 PAD21.1(P)
N$54: E15.11(E:I) PAD12.1(P)
N$55: E15.10(E:O) PAD13.1(P)
N$56: E15.13(F:I) PAD14.1(P)
N$57: E15.12(F:O) PAD15.1(P)
N$58: E44.5 PAD22.1(P)
N$59: E44.6 PAD23.1(P)
N$60: E44.7 PAD24.1(P)
N$61: E44.8 PAD25.1(P)
N$62: E44.16 PAD26.1(P)
N$63: E44.15 PAD37.1(P)
N$64: E44.14 PAD38.1(P)
N$65: E44.13 PAD39.1(P)
N$66: E44.12 PAD40.1(P)
N$69: E44.11 PAD41.1(P)
N$70: E44.10 PAD45.1(P)
N$71: E3.3(B:I0) PAD27.1(P)
N$72: E3.4(B:I1) PAD28.1(P)
N$74: E3.5(B:I2) PAD29.1(P)
N$75: E3.6(B:O) PAD30.1(P)
N$76: E29.9(C:I0) PAD31.1(P)
N$77: E29.10(C:I1) PAD32.1(P)
N$78: E29.8(C:O) PAD33.1(P)
N$79: E29.12(D:I0) PAD34.1(P)
N$80: E29.13(D:I1) PAD35.1(P)
N$81: E29.11(D:O) PAD36.1(P)
N$82: E44.9 PAD46.1(P)
N$83: E13.1 PAD47.1(P)
N$84: E13.2 PAD48.1(P)
N$85: E13.3 PAD49.1(P)
N$86: E13.4 PAD50.1(P)
N$87: E39.12(D:I0) PAD42.1(P)
N$88: E39.13(D:I1) PAD43.1(P)
N$89: E39.11(D:O) PAD44.1(P)
N$90: E13.5 PAD51.1(P)
N$91: E13.6 PAD52.1(P)
N$92: E13.7 PAD53.1(P)
N$93: E13.8 PAD54.1(P)
N$95: E13.16 PAD55.1(P)
N$96: E13.15 PAD56.1(P)
N$97: E13.14 PAD57.1(P)
N$98: E13.13 PAD58.1(P)
N$99: E13.12 PAD59.1(P)
N$100: E13.11 PAD60.1(P)
N$101: E13.10 PAD61.1(P)
N$102: E13.9 PAD62.1(P)
VCC [Power]: C6.1 C7.1 C8.1 C9.1 C10.1 C11.1 C12.1 C13.1 C14.1 C15.1 C16.1 C17.1 C18.1 C19.1 C20.1 C21.1 C22.1 C23.1 C24.1 C25.1 C26.1 C27.1 C28.1 C29.1 C30.1 C31.1 C32.1 C33.1 C34.1 C35.1 C36.1 C37.1 C38.1 C39.1 C40.1 C41.1 C42.1 C43.1 C44.1 C45.1 C46.1 C47.1 C48.1 C49.+ C50.+ C51.+ C52.+ E4.2(VCC) E10.28(VCC) E16.28(VCC) VCC.1(P) ; also sheet 4
Unconnected: E10.18(I/O6) E10.19(I/O7) E16.18(I/O6) E16.19(I/O7) E38.12(A:Y4)

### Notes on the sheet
- Spares:
- Unused Gates:
- Omnibus Memory Connectors

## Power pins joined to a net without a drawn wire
GND: E1.10(P:GND) E2.7(P:GND) E3.7(P:GND) E5.7(P:GND) E6.7(P:GND) E7.7(P:GND) E8.7(P:GND) E9.7(P:GND) E11.7(P:GND) E12.7(P:GND) E14.10(P:GND) E15.7(P:GND) E17.7(P:GND) E18.7(P:GND) E19.4(P:GND) E20.4(P:GND) E21.4(P:GND) E22.4(GND) E24.10(P:GND) E25.4(P:GND) E26.4(P:GND) E27.4(P:GND) E28.7(GND) E29.7(P:GND) E30.7(GND) E31.7(P:GND) E32.4(P:GND) E33.4(P:GND) E34.4(P:GND) E35.4(GND) E36.4(P:GND) E37.4(P:GND) E38.10(P:GND) E39.7(P:GND) E40.4(P:GND) E41.4(P:GND) E42.7(P:GND) E43.7(P:GND)
VCC: E1.20(P:VCC) E2.14(P:VCC) E3.14(P:VCC) E5.14(P:VCC) E6.14(P:VCC) E7.14(P:VCC) E8.14(P:VCC) E9.14(P:VCC) E11.14(P:VCC) E12.14(P:VCC) E14.20(P:VCC) E15.14(P:VCC) E17.14(P:VCC) E18.14(P:VCC) E19.8(P:VCC) E20.8(P:VCC) E21.8(P:VCC) E22.8(VCC) E24.20(P:VCC) E25.8(P:VCC) E26.8(P:VCC) E27.8(P:VCC) E28.14(VCC) E29.14(P:VCC) E30.14(VCC) E31.14(P:VCC) E32.8(P:VCC) E33.8(P:VCC) E34.8(P:VCC) E35.8(VCC) E36.8(P:VCC) E37.8(P:VCC) E38.20(P:VCC) E39.14(P:VCC) E40.8(P:VCC) E41.8(P:VCC) E42.14(P:VCC) E43.14(P:VCC)

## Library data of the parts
C2 C4-C48 = rcl:C-US: CAPACITOR, American symbol
C49-C52 = rcl:CPOL-US: POLARIZED CAPACITOR, American symbol
D2 D4 D5 = diode:1N4148: DIODE
E1 E14 E24 E38 = 74xx-jameco:74*240: Octal BUFFER and LINE DRIVER, 3-state
E2 E5 E6 E9 E12 E17 E18 E42 E43 = 74xx-jameco:74*74: Dual D type positive edge triggered FLIP FLOP, preset and clear
E3 E11 = 74xx-jameco:74*10: Triple 3-input NAND gate
E4 = maxim:MAX702CPA: POWER SUPPLY MONITOR
E7 E15 = 74xx-jameco:74*04: Hex INVERTER
E8 E29 E31 E39 = 74xx-jameco:74*00: Quad 2-input NAND gate
E10 E16 = memory-hitachi:62256P: MEMORY
E13 E44 = ic-package:DIL16: Dual In Line
E19-E21 E25-E27 E32-E34 E36 E37 E40 E41 = 74xx-jameco:DS75453: Quad 2-input NAND gate, open collector output
E22 E35 = maxim:MXD1000: DELAY LINE
E28 E30 = maxim:MXD1000P: DELAY LINE
GND VCC = wirepad:2,15/1,0: THROUGH-HOLE PAD
H01/H20 H02/H21 H03/H22 H04/H23 H05/H24 = con-lstb:MA17-2: PIN HEADER
JP1 JP3 = jumper:JP2Q: JUMPER
JP2 JP4 = jumper:JP3Q: JUMPER
PAD1-PAD62 = wirepad:1,6/0,8: THROUGH-HOLE PAD
R15-R18 R21 R22 R27-R30 = rcl:R-US_: RESISTOR, American symbol

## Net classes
1 Power: width 0.635 mm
